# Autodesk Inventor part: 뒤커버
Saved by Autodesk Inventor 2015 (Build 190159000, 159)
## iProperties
Created: 2025-08
Part Number: 뒤커버
Material: 일반
Document SubType Name: Modeling
Designer: USER
Density: 1 g/cm^3
Appearance: 기본값
Author: USER
Author: jhkim
Creation Date: 2025-08-05
Sending System: Autodesk Inventor 2026
Preprocessor: ST-DEVELOPER v20.1
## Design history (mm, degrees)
node "뒤커버1"
node "솔리드1"
node "기준1"
